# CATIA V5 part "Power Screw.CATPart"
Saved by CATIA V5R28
Part number: Power Screw
Bounding box of the stored display mesh (mm): x -17.321 to 17.321, y -20 to 20, z -550 to 500.879
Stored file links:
  C:\Users\Parisa\Desktop\tarah sanat\CAR JACK\Power Screw.CATPart
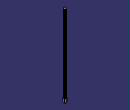
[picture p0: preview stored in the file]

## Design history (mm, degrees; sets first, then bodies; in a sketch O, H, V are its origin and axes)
Body1 (main body)
  Sketch1 on xy-plane, origin (0, 0, 0), H (1, 0, 0), V (0, 1, 0)
    circle A1 centre (0, 0) radius 15
    radius A1 = 15
  Pad1: profile Sketch1, direction (0, 0, 1), length 500, mirrored extent
  Helix1: Direction Z axis, RefPoint {point type OnCurve, Support edge [face of Pad1 from Sketch1.A1 | end face of Pad1], RefPoint {extremum Reference edge [face of Pad1 from Sketch1.A1 | end face of Pad1], Direction (1, 2, 3)}, Length 0}, Pitch 7, Height 1000, TaperAngle 0, Revolutions 1
  Plane1: type 1Line1Pt, RefPoint vertex of Helix1, Line Y axis
  Sketch2 on Plane1, origin (0, 0, 0), H (0, -1, 0), V (0.0126, 0, 0.9999)
    point P1 (-13.6097, -500.0398)
    line L1 (-12.8597, -499.2898) -> (-12.8597, -500.7898)
    line L2 (-12.8597, -500.7898) -> (-14.3597, -500.7898)
    line L3 (-14.3597, -500.7898) -> (-14.3597, -499.2898)
    line L4 (-14.3597, -499.2898) -> (-12.8597, -499.2898)
    reference projected point E1 (-13.6097, -500.0398) from vertex of Helix1
    length L4 = 1.5
    length L3 = 1.5
    vertical: L1 V, L3 V
    horizontal: L2 H, L4 H
    equidistance: L1 L3 P1, L2 L4 P1
    coincidence: P1 E1
  Rib1: profile Sketch2, centre curve Helix1
  Sketch3 on start face of Pad1, origin (0, 0, -500), H (1, 0, 0), V (0, -1, 0)
    point P1 (17.3205, 0)
    construction circle A1 centre (0, 0) radius 20
    construction circle A2 centre (0, 0) radius 17.3205
    point P2 (17.3205, -10)
    point P3 (17.3205, 10)
    point P4 (0, 20)
    point P5 (-17.3205, 10)
    point P6 (-17.3205, -10)
    point P7 (0, -20)
    line L1 (17.3205, -10) -> (17.3205, 10)
    line L2 (17.3205, 10) -> (0, 20)
    line L3 (0, 20) -> (-17.3205, 10)
    line L4 (-17.3205, 10) -> (-17.3205, -10)
    line L5 (-17.3205, -10) -> (0, -20)
    line L6 (0, -20) -> (17.3205, -10)
    construction line L7 (0, 0) -> (17.3205, 0)
    length L2 = 20
    coincidence: A1 P2, A1 P3, A1 P4, A1 P5, A1 P6, A1 P7
    tangency: A2 L1, A2 L2, A2 L3, A2 L4, A2 L5, A2 L6
    midpoint: P1 L1
    horizontal: L7 H
  Pad2: profile Sketch3, direction (0, 0, -1), length 50
  Sketch4 on face of Pad2 from Sketch3.L5, origin (-8.6603, 15, 0), H (-0.866, -0.5, 0), V (0, 0, 1)
    circle A1 centre (0, -525) radius 10
    point P1 (0, -525)
    reference projected line E1 (10, -550) -> (-10, -550) from edge [face of Pad2 from Sketch3.L5 | end face of Pad2]
    radius A1 = 10
    distance P1 E1 = 25
    coincidence: P1 V
  Pocket1: profile Sketch4, direction (0.5, -0.866, 0), length 50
